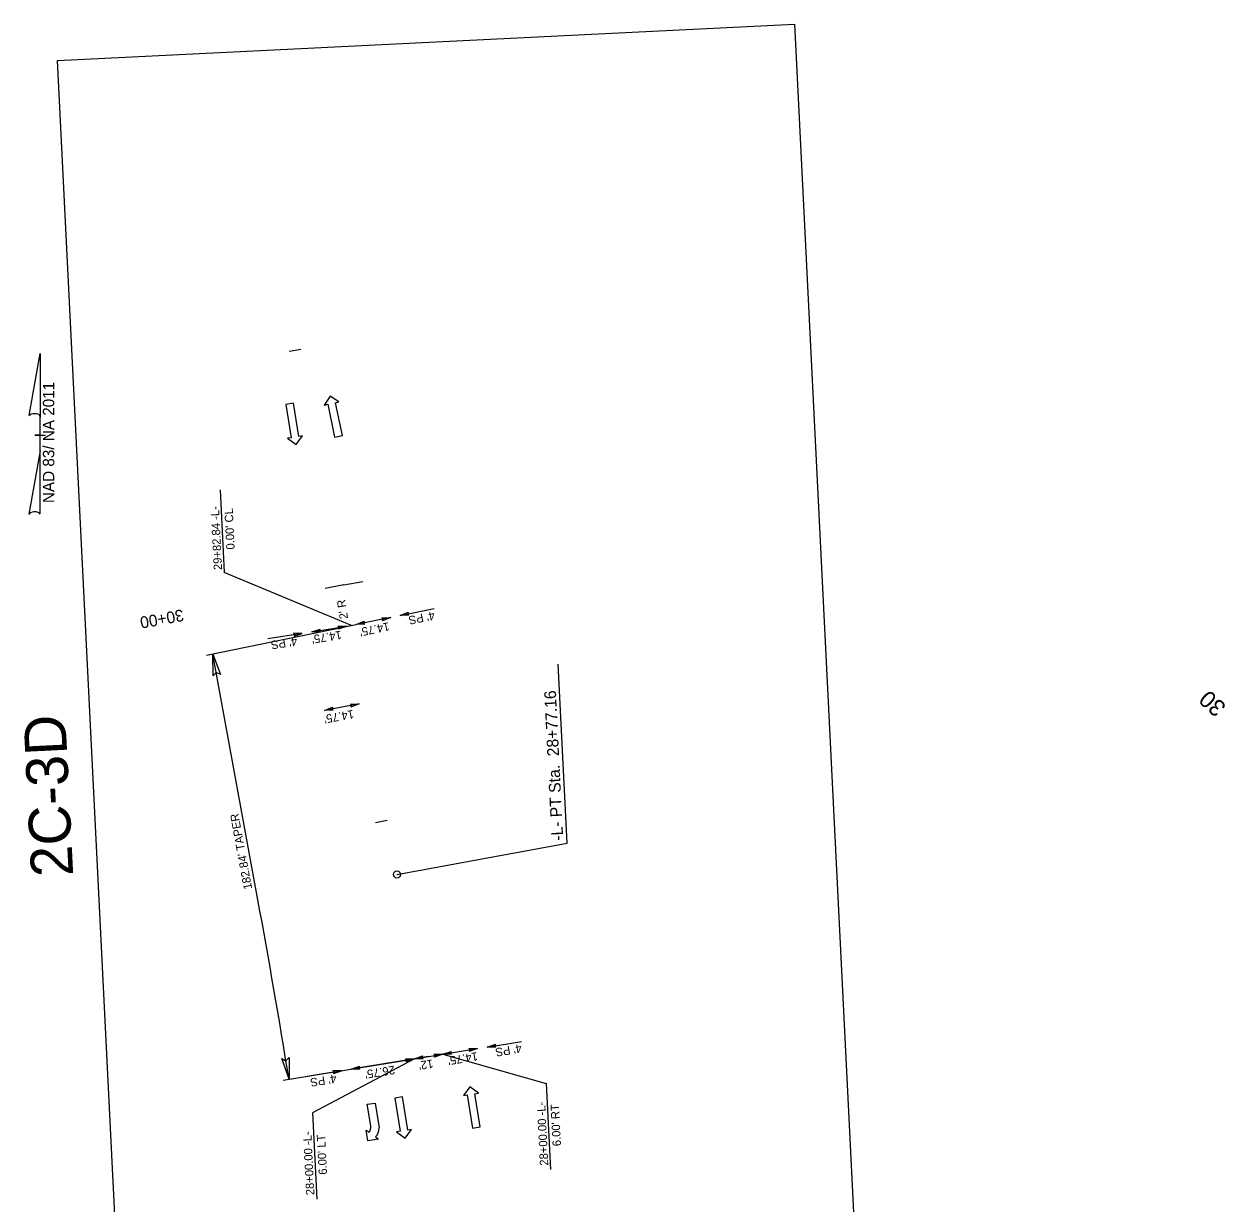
# Model space of a CAD drawing. Extents: x 1807485 to 1808169, y 913841 to 915733.
# Drawn here: x 1807668 to 1808169, y 915241 to 915733 of the extents above; entities that cross this region are included whole.
import ezdxf

# ---------------------------------------------------------------- set-up
doc = ezdxf.new("R2010")
doc.units = 0
for name, color, linetype in [('Prop Dimension', 7, 'Continuous'), ('Prop Horizontal Alignment Station Label', 7, 'Continuous'), ('Prop Horizontal Alignment Tick Label', 7, 'Continuous'), ('Prop Horizontal Alignment Tick Large', 7, 'Continuous'), ('Prop Horizontal Alignment Tick Small', 7, 'Continuous'), ('Prop Lane Arrow CELL', 7, 'Continuous'), ('Prop North Arrow NAD83 for Plan Sheets CELL', 7, 'Continuous'), ('Prop Terminator CELL', 7, 'Continuous'), ('Scratch_Level_3', 7, 'Continuous'), ('Scratch_Level_6', 7, 'Continuous')]:
    doc.layers.add(name, color=color, linetype=linetype)

msp = doc.modelspace()

# ---------------------------------------------------------------- linework, layer by layer
at = {"layer": 'Prop Dimension'}
for p, q in [((1807749.52, 915538.59), (1807751.23, 915504.13)), ((1807804.25, 915482.04), (1807751.23, 915504.13)), ((1807743.85, 915469.56), (1807806.22, 915482.4)), ((1807765.26, 915367.47), (1807746.46, 915470.1)), ((1807775.77, 915292.15), (1807830.53, 915301.1)), ((1807830.53, 915301.1), (1807788.02, 915278.53)), ((1807842.38, 915303.03), (1807885.62, 915290.86)), ((1807885.62, 915290.86), (1807887.4, 915254.9)), ((1807788.02, 915278.53), (1807789.8, 915242.56))]:
    msp.add_line(p, q, dxfattribs=at)
msp.add_arc((1803888.72, 914657.58), 3941, 9.27189, 10.37717, dxfattribs=at)
at = {"layer": 'Prop Horizontal Alignment Station Label'}
for p, q in [((1807894.34, 915391.1), (1807890.63, 915465.8)), ((1807823.29, 915378.09), (1807894.34, 915391.1))]:
    msp.add_line(p, q, dxfattribs=at)
msp.add_circle((1807823.29, 915378.09), 1.5, dxfattribs=at)
at = {"layer": 'Prop Horizontal Alignment Tick Large'}
for q in [(1807793.29, 915497.48), (1807809.03, 915500.36)]:
    msp.add_line((1807801.16, 915498.92), q, dxfattribs=at)
at = {"layer": 'Prop Horizontal Alignment Tick Small'}
for p, q in [((1807783.15, 915597.28), (1807778.23, 915596.38)), ((1807819.18, 915400.56), (1807814.26, 915399.66)), ((1807836.46, 915302.06), (1807831.52, 915301.26))]:
    msp.add_line(p, q, dxfattribs=at)
at = {"layer": 'Prop Lane Arrow CELL'}
for p, q in [((1807780.14, 915574.75), (1807776.88, 915574.23)), ((1807776.88, 915574.23), (1807779.09, 915560.4)), ((1807782.35, 915560.93), (1807780.14, 915574.75)), ((1807795.38, 915577.77), (1807792.9, 915574.02)), ((1807792.9, 915574.02), (1807794.37, 915574.33)), ((1807794.37, 915574.33), (1807797.27, 915560.64)), ((1807799.07, 915575.33), (1807795.38, 915577.77)), ((1807797.6, 915575.02), (1807799.07, 915575.33)), ((1807800.5, 915561.32), (1807797.6, 915575.02)), ((1807779.09, 915560.4), (1807777.61, 915560.17)), ((1807777.61, 915560.17), (1807781.17, 915557.55)), ((1807781.17, 915557.55), (1807783.83, 915561.16)), ((1807783.83, 915561.16), (1807782.35, 915560.93)), ((1807797.27, 915560.64), (1807800.5, 915561.32)), ((1807853.73, 915289.42), (1807851.07, 915285.81)), ((1807857.29, 915286.8), (1807853.73, 915289.42)), ((1807825.62, 915285.2), (1807822.36, 915284.68)), ((1807822.36, 915284.68), (1807824.58, 915270.86)), ((1807827.84, 915271.38), (1807825.62, 915285.2)), ((1807851.07, 915285.81), (1807852.55, 915286.04)), ((1807852.55, 915286.04), (1807854.76, 915272.22)), ((1807855.81, 915286.57), (1807857.29, 915286.8)), ((1807858.02, 915272.74), (1807855.81, 915286.57)), ((1807810.91, 915282.14), (1807814.17, 915282.66)), ((1807812.36, 915273.11), (1807810.91, 915282.14)), ((1807814.17, 915282.66), (1807815.85, 915272.25)), ((1807811.19, 915266.89), (1807810.42, 915271.33)), ((1807810.42, 915271.33), (1807811.63, 915270.46)), ((1807814.32, 915268.51), (1807815.52, 915267.64)), ((1807824.58, 915270.86), (1807823.1, 915270.62)), ((1807823.1, 915270.62), (1807826.65, 915268)), ((1807826.65, 915268), (1807829.32, 915271.62)), ((1807829.32, 915271.62), (1807827.84, 915271.38)), ((1807854.76, 915272.22), (1807858.02, 915272.74)), ((1807815.52, 915267.64), (1807811.19, 915266.89))]:
    msp.add_line(p, q, dxfattribs=at)
for centre, radius, start, end in [((1807809.15, 915272.58), 3.27, 319.4817, 9.1398), ((1807810.61, 915272.21), 5.25, 315.1521, 0.4638)]:
    msp.add_arc(centre, radius, start, end, dxfattribs=at)
at = {"layer": 'Prop North Arrow NAD83 for Plan Sheets CELL'}
for p, q in [((1807669.73, 915569.6), (1807674.33, 915595.55)), ((1807674.35, 915595.55), (1807674.33, 915595.55)), ((1807674.35, 915595.55), (1807674.33, 915595.55)), ((1807674.35, 915595.55), (1807674.35, 915568.79)), ((1807674.35, 915554.9), (1807674.35, 915569.57)), ((1807674.35, 915568.79), (1807674.35, 915569.54)), ((1807672.11, 915561.39), (1807672.09, 915561.39)), ((1807674.1, 915561.39), (1807672.11, 915561.39)), ((1807672.14, 915561.39), (1807676.62, 915561.39)), ((1807674.35, 915554.9), (1807669.68, 915528.44)), ((1807674.38, 915528.55), (1807674.35, 915554.9))]:
    msp.add_line(p, q, dxfattribs=at)
for centre, start_param, end_param in [((1807672.05, 915569.32), 0.216388, 2.908219), ((1807672.05, 915528.34), 0.201328, 3.141593)]:
    msp.add_ellipse(centre, major_axis=(2.37, -0.02), ratio=0.461098, start_param=start_param, end_param=end_param, dxfattribs=at)
at = {"layer": 'Prop Terminator CELL'}
for points in [[(1807746.56, 915460.96), (1807746.46, 915470.1), (1807749.67, 915461.48), (1807747.89, 915462.33)], [(1807778.31, 915301.69), (1807778.23, 915292.56), (1807775.19, 915301.23), (1807776.96, 915300.35)], [(1807807.79, 915296.75), (1807804.13, 915296.79), (1807807.6, 915298), (1807807.25, 915297.29)]]:
    msp.add_lwpolyline(points, close=True, dxfattribs=at)
at = {"layer": 'Scratch_Level_3'}
msp.add_lwpolyline([(1807728.07, 914781.87), (1807681.6, 915717.81), (1807989.22, 915733.08), (1808035.69, 914797.14)], close=True, dxfattribs=at)
at = {"layer": 'Scratch_Level_6'}
for p, q in [((1807824.58, 915486.18), (1807838.8, 915489.1)), ((1807820.67, 915485.37), (1807806.22, 915482.4)), ((1807787.73, 915479.34), (1807802.29, 915481.68)), ((1807783.78, 915478.7), (1807769.44, 915476.4)), ((1807807.49, 915449.25), (1807792.99, 915446.59)), ((1807842.38, 915303.03), (1807856.93, 915305.41)), ((1807860.88, 915306.05), (1807875.21, 915308.39)), ((1807830.53, 915301.1), (1807804.13, 915296.79)), ((1807830.53, 915301.1), (1807842.38, 915303.03)), ((1807800.19, 915296.14), (1807785.86, 915293.8))]:
    msp.add_line(p, q, dxfattribs=at)
for points in [[(1807817.01, 915485.25), (1807820.67, 915485.37), (1807817.25, 915484.01), (1807817.57, 915484.73)], [(1807828.24, 915486.29), (1807824.58, 915486.18), (1807828, 915487.53), (1807827.68, 915486.81)], [(1807791.38, 915479.3), (1807787.73, 915479.34), (1807791.2, 915480.54), (1807790.85, 915479.84)], [(1807798.63, 915481.72), (1807802.29, 915481.68), (1807798.81, 915480.47), (1807799.17, 915481.17)], [(1807809.87, 915482.52), (1807806.22, 915482.4), (1807809.64, 915483.75), (1807809.32, 915483.03)], [(1807780.32, 915477.52), (1807783.78, 915478.7), (1807780.1, 915478.76), (1807780.66, 915478.2)], [(1807803.84, 915449.21), (1807807.49, 915449.25), (1807804.05, 915447.97), (1807804.39, 915448.68)], [(1807796.64, 915446.63), (1807792.99, 915446.59), (1807796.43, 915447.87), (1807796.09, 915447.16)], [(1807846.03, 915303), (1807842.38, 915303.03), (1807845.85, 915304.24), (1807845.5, 915303.54)], [(1807853.28, 915305.44), (1807856.93, 915305.41), (1807853.46, 915304.19), (1807853.82, 915304.9)], [(1807864.53, 915306.02), (1807860.88, 915306.05), (1807864.35, 915307.26), (1807864, 915306.56)], [(1807826.88, 915301.13), (1807830.53, 915301.1), (1807827.06, 915299.88), (1807827.41, 915300.59)], [(1807834.19, 915301.06), (1807830.53, 915301.1), (1807834, 915302.31), (1807833.65, 915301.6)], [(1807838.72, 915303.06), (1807842.38, 915303.03), (1807838.91, 915301.81), (1807839.26, 915302.52)], [(1807796.73, 915294.95), (1807800.19, 915296.14), (1807796.51, 915296.19), (1807797.07, 915295.63)]]:
    msp.add_lwpolyline(points, close=True, dxfattribs=at)

# ---------------------------------------------------------------- texts
at = {"layer": 'Prop Dimension'}
for s, rotation, p in [('29+82.84 -L-', 92.8422, (1807750.31, 915505.23)), ("0.00' CL", 92.8422, (1807755.58, 915513.8)), ("2' R", 98.9129, (1807802.9, 915484.96)), ("182.84' TAPER", 100.3772, (1807762.85, 915372.18)), ('28+00.00 -L-', 92.8422, (1807886.45, 915256.62)), ("6.00' RT", 92.8422, (1807891.75, 915264.73)), ('28+00.00 -L-', 92.8422, (1807788.85, 915244.28)), ("6.00' LT", 92.8422, (1807794.12, 915252.83))]:
    msp.add_text(s, height=3.5, rotation=rotation, dxfattribs=at).set_placement(p)
at = {"layer": 'Prop Horizontal Alignment Station Label'}
msp.add_text('-L- PT Sta.  28+77.16', height=4.9, rotation=92.8422, dxfattribs=at).set_placement((1807892.71, 915392.27))
at = {"layer": 'Prop Horizontal Alignment Tick Label'}
for s, height, rotation, p in [('30+00', 4.9, 190.3772, (1807733.8, 915488.82)), ('30', 7, 137.6532, (1808169.79, 915448.46))]:
    msp.add_text(s, height=height, rotation=rotation, dxfattribs=at).set_placement(p)
at = {"layer": 'Prop North Arrow NAD83 for Plan Sheets CELL'}
msp.add_text('NAD 83/ NA 2011', height=4.76, rotation=90, dxfattribs=at).set_placement((1807680.25, 915533.11))
at = {"layer": 'Scratch_Level_3'}
msp.add_text('2C-3D', height=17.5, rotation=92.8422, dxfattribs=at).set_placement((1807688.18, 915377.58))
at = {"layer": 'Scratch_Level_6'}
for s, rotation, p in [("4' PS", 191.6303, (1807838.69, 915487.97)), ("14.75'", 189.124, (1807799.92, 915479.85)), ("14.75'", 191.6303, (1807819.76, 915483.4)), ("4' PS", 189.124, (1807781.35, 915477.21)), ("14.75'", 190.3772, (1807804.98, 915446.81)), ("14.75'", 189.2719, (1807856.72, 915303.94)), ("4' PS", 189.2719, (1807875.05, 915307.26)), ("12'", 189.2719, (1807838.12, 915300.9)), ("4' PS", 189.2719, (1807797.76, 915294.65)), ("26.75'", 189.2719, (1807822.13, 915298.29))]:
    msp.add_text(s, height=3.5, rotation=rotation, dxfattribs=at).set_placement(p)

doc.saveas('drawing.dxf')
